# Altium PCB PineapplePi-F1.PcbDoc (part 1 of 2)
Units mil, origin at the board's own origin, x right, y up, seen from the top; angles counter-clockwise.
Board outline 1965 x 3150 mil, 2 copper layers (Top Layer, Bottom Layer); 93 components, 95 nets, 510 pads, 397 vias.
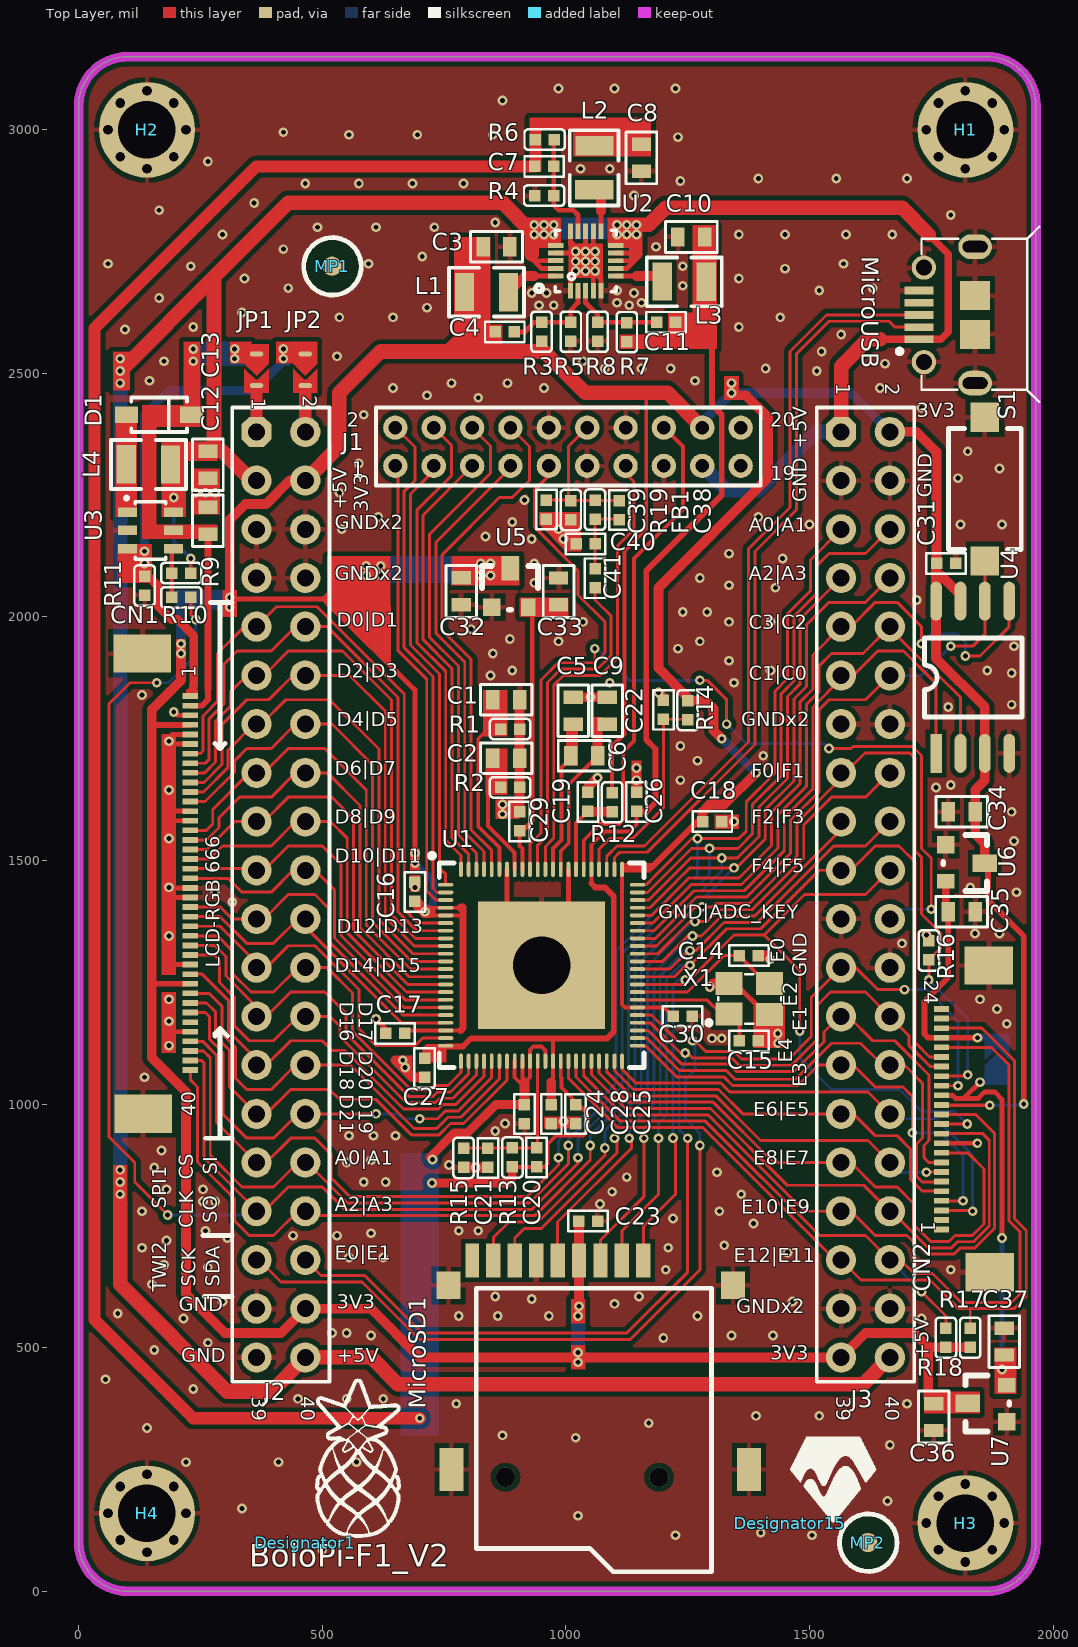
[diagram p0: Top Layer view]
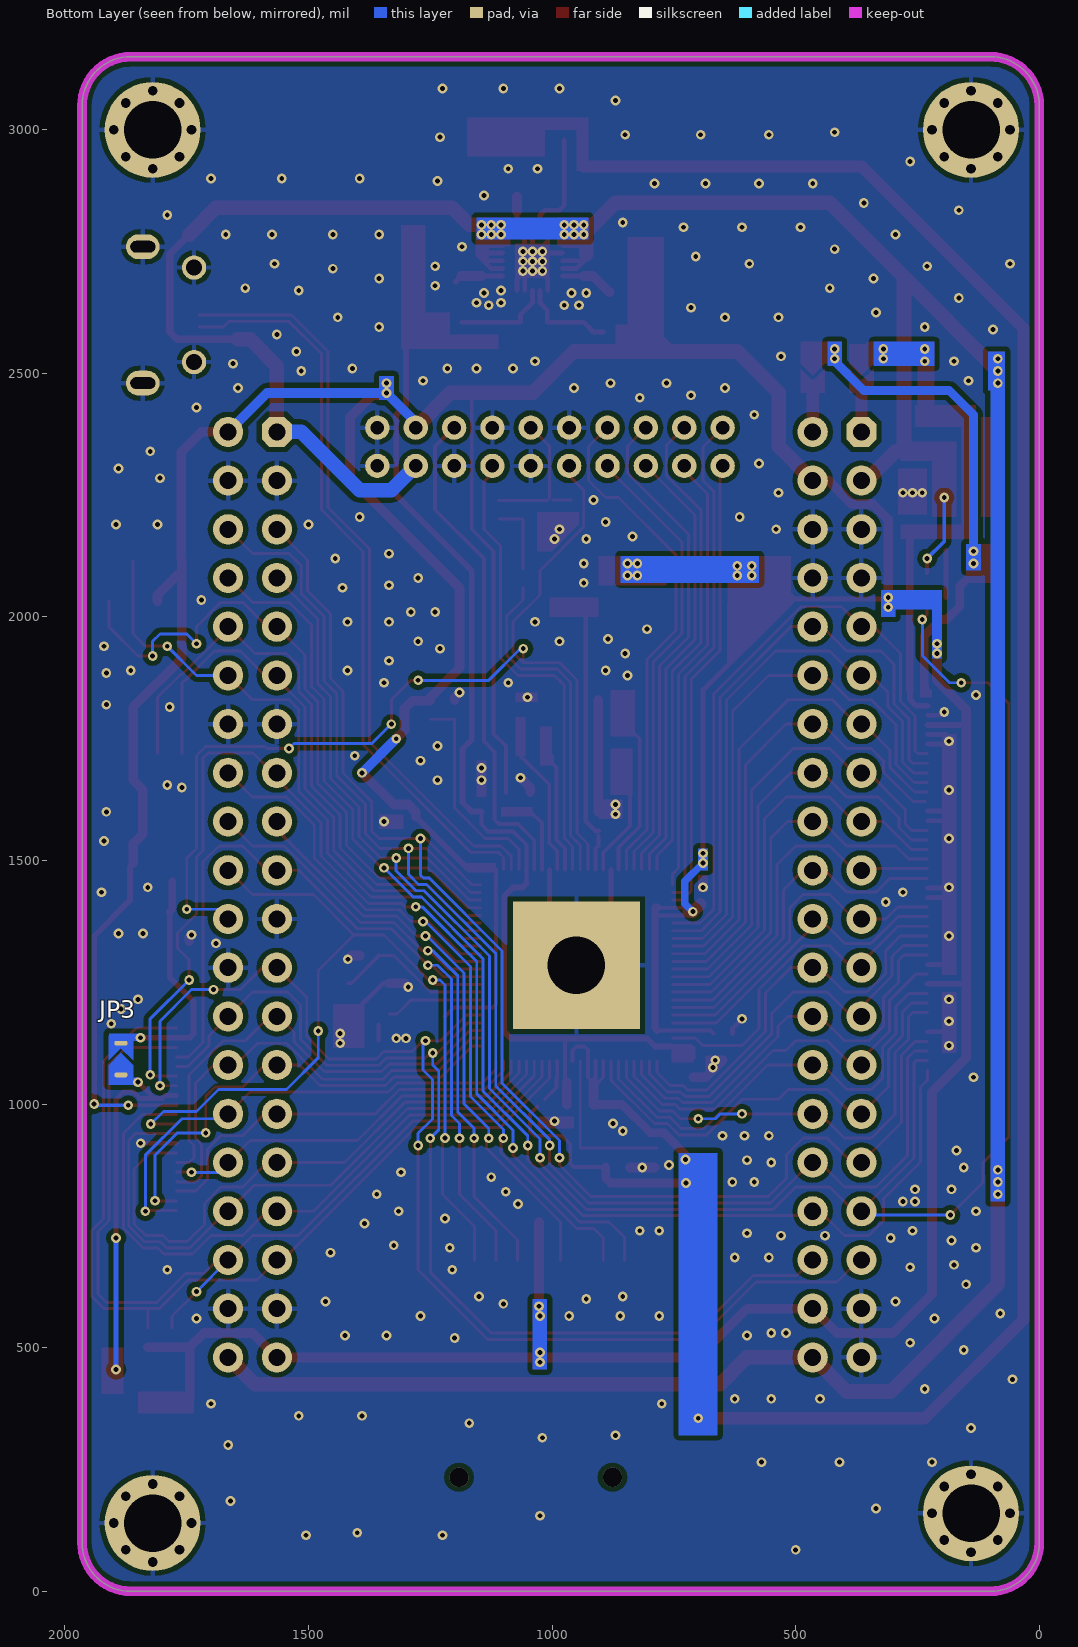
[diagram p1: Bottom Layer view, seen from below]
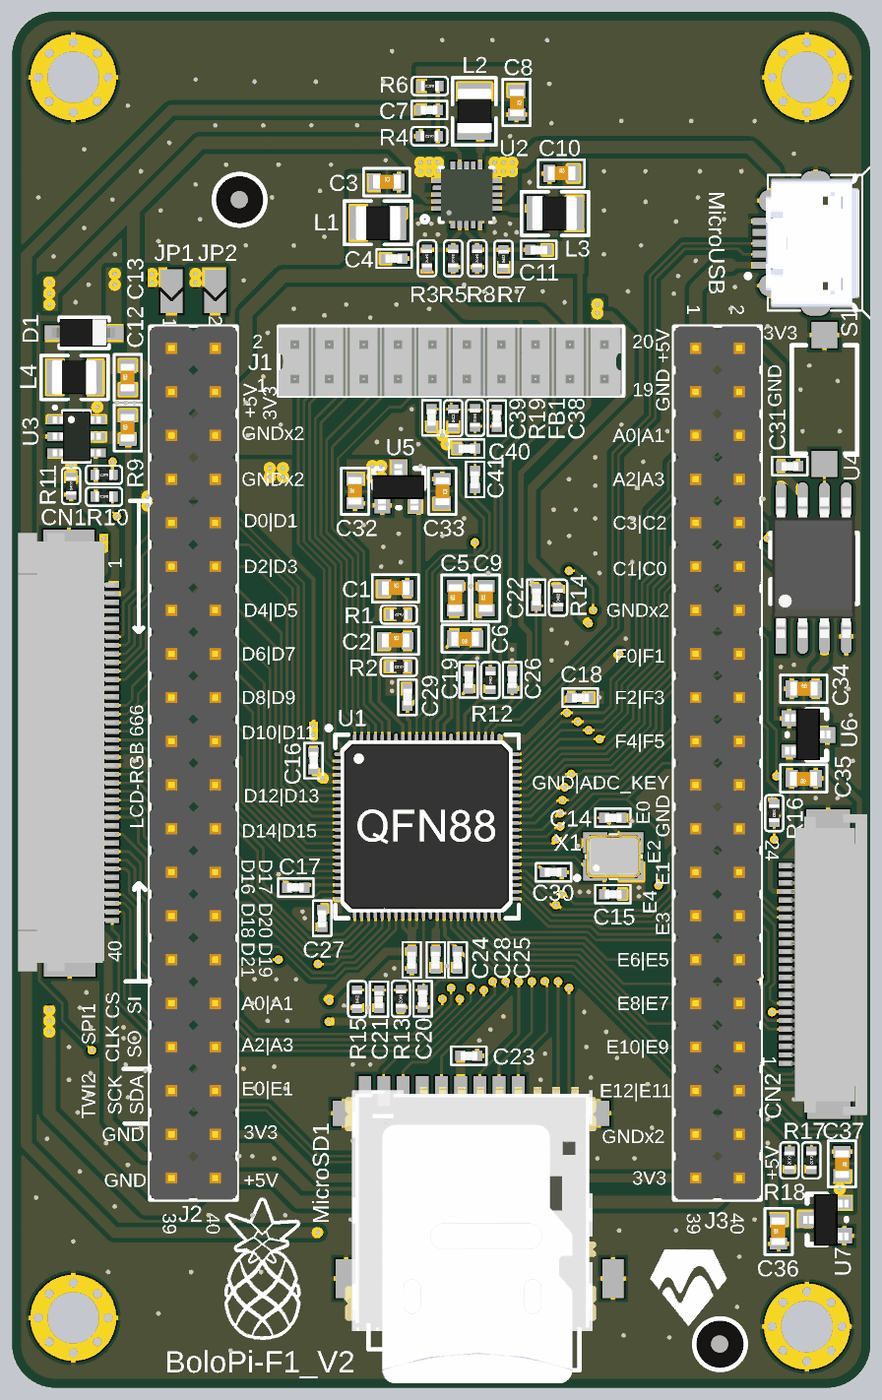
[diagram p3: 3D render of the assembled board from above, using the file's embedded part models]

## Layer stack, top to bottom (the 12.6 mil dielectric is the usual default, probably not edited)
Top Layer: signal copper 1.4
Dielectric: dielectric 12.6, FR-4, Dk 4.8
Bottom Layer: signal copper 1.4

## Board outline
0,100 ccw(c100,100) 100,0 1865,0 ccw(c1865,100) 1965,100 1965,3050 ccw(c1865,3050) 1865,3150 100,3150 ccw(c100,3050) 0,3050

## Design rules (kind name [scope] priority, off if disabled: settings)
Clearance [All] p1: gap=10
PolygonConnect [InNet('AGND') vs IsVia] p1: connectstyle=Direct reliefconductorwidth=10 reliefentries=4 polygonreliefangle="90 Angle"
PolygonConnect PolygonConnect_1 [All] p2: connectstyle=Relief reliefconductorwidth=10 reliefentries=4 polygonreliefangle="90 Angle"
RoutingVias [All] p1: holewidth=28 width=50 viastyle="Through Hole" minholewidth=28 minwidth=50 maxholewidth=28 maxwidth=50
SilkscreenOverComponentPads [All] p1: minsilkscreentomaskgap=10
SolderMaskExpansion [All] p1: expansion=4
Width [All] p1: maxlimit=50 minlimit=6 preferedwidth=30
27 further rules are at their usual default settings.

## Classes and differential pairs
component class PineapplePi-F1: C1 C2 C3 C4 C5 C6 C7 C8 C9 C10 C11 C12 C13 C14 C15 C16 C17 C18 C19 C20 C21 C22 C23 C24 C25 C26 C27 C28 C29 C30 C31 C32 C33 C34 C35 C36 C37 C38 C39 C40 C41 CN1 CN2 D1 FB1 J1 J2 J3 JP1 JP2 JP3 L1 L2 L3 L4 MicroSD1 MicroUSB MP1 MP2 R1 R2 R3 R4 R5 R6 R7 R8 R9 R10 R11 R12 R13 R14 R15 R16 R17 R18 R19 S1 U1 U2 U3 U4 U5 U6 U7 X1

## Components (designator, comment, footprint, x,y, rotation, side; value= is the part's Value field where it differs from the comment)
C1 "0402" 0603AC 850,1830 r0 top
C2 "0402" 0603AC 850,1710 r0 top
C3 "0402" 0603AC 830,2760 r0 top
C4 "0402" 0402AC 855,2585 r0 top
C5 "0402" 0603AC 1015,1780 r90 top
C6 "0402" 0603AC 1065,1715 r180 top
C7 "0402" 0402AC 936,2925 r0 top
C8 "0402" 0603AC 1155,2970 r270 top
C9 "0402" 0603AC 1085,1780 r90 top
C10 "0402" 0603AC 1230,2780 r0 top
C11 "0402" 0402AC 1225,2605 r180 top
C12 "0402" 0603AC 265,2170 r90 top
C13 "0402" 0603AC 265,2285 r90 top
C14 "0402" 0402AC 1395,1305 r180 top
C15 "0402" 0402AC 1395,1130 r180 top
C16 "0402" 0402AC 690,1455 r270 top
C17 "0402" 0402AC 630,1145 r0 top
C18 "0402" 0402AC 1320,1580 r180 top
C19 "0402" 0402AC 1045,1640 r270 top
C20 "0402" 0402AC 940,910 r270 top
C21 "0402" 0402AC 840,870 r90 top
C22 "0402" 0402AC 1200,1829 r270 top
C23 "0402" 0402AC 1065,760 r180 top
C24 "0402" 0402AC 915,960 r90 top
C25 "0402" 0402AC 1020,960 r90 top
C26 "0402" 0402AC 1145,1640 r270 top
C27 "0402" 0402AC 710,1055 r90 top
C28 "0402" 0402AC 970,960 r90 top
C29 "0402" 0402AC 905,1600 r270 top
C30 "0402" 0402AC 1220,1180 r0 top
C31 "0402" 0402AC 1800,2110 r180 top
C32 "0402" 0603AC 785,2025 r90 top
C33 "0402" 0603AC 985,2080 r270 top
C34 "0402" 0603AC 1785,1600 r0 top
C35 "0402" 0603AC 1840,1395 r180 top
C36 "0402" 0603AC 1755,330 r90 top
C37 "0402" 0603AC 1900,540 r270 top
C38 "0402" 0402AC 1110,2200 r90 top
C39 "0402" 0402AC 960,2240 r270 top
C40 "0402" 0402AC 1060,2150 r180 top
C41 "0402" 0402AC 1060,2060 r90 top
CN1 "RGB_LCD_40P" FH19C-40S-0.5SH 130,1925 r270 top
CN2 "Header 24" FH19C-24S-0.5SH 1870,655 r90 top
D1 "Diode" SOD123 165,2415 r180 top
Designator1 "Comment" ? 465,100 r0 top
Designator15 "Comment" 4.5MM-Digital-OVERLAY 1460,140 r0 top
FB1 "CD43" 0402AR 1060,2240 r270 top
H1 "M3-HOLE" M3-HOLE 1820,3000 r0 top
H2 "M3-HOLE" M3-HOLE 140,3000 r0 top
H3 "M3-HOLE" M3-HOLE 1820,140 r0 top
H4 "M3-HOLE" M3-HOLE 140,160 r0 top
J1 "Header 10X2" HDR2X10-2.0mm 650,2310 r0 top
J2 "Header 20X2" HDR2X20 365,2380 r270 top
J3 "Header 20X2" HDR2X20 1565,2380 r270 top
JP1 "SW-PAD-2" SW-PAD-2 340,2560 r270 top
JP2 "SW-PAD-2" SW-PAD-2 440,2560 r270 top
JP3 "SW-PAD-2" SW-PAD-2 1860,1040 r90 bottom
L1 "CD43" 2520 840,2665 r0 top
L2 "CD43" 2520 1060,2925 r90 top
L3 "CD43" 2520 1240,2690 r180 top
L4 "CD43" 2520 140,2315 r180 top
MicroSD1 "MicroSD" MicroSD 780,240 r0 top
MicroUSB "MicroUSB-DIP" MICRO_USB_DIP 1840,2480 r90 top (schematic designator MicroUSB-DIP1)
MP1 "MARKPOINT" MARKPOINT 520,2720 r0 top
MP2 "MARKPOINT" MARKPOINT 1620,100 r0 top
R1 "0402" 0402AR 905,1770 r180 top
R2 "0402" 0402AR 905,1650 r180 top
R3 "0402" 0402AR 950,2605 r270 top
R4 "0402" 0402AR 975,2865 r180 top
R5 "0402" 0402AR 1010,2605 r270 top
R6 "0402" 0402AR 976,2980 r180 top
R7 "0402" 0402AR 1125,2565 r90 top
R8 "0402" 0402AR 1065,2605 r270 top
R9 "0402" 0402AR 230,2090 r180 top
R10 "0402" 0402AR 230,2040 r180 top
R11 "0402" 0402AR 135,2045 r90 top
R12 "0402" 0402AR 1095,1600 r90 top
R13 "0402" 0402AR 890,910 r270 top
R14 "0402" 0402AR 1250,1789 r90 top
R15 "0402" 0402AR 790,870 r90 top
R16 "0402" 0402AR 1745,1335 r270 top
R17 "0402" 0402AR 1830,540 r270 top
R18 "0402" 0402AR 1780,540 r270 top
R19 "0402" 0402AR 1010,2200 r90 top
S1 "SW-PB" SW-SMD1 1860,2110 r90 top
U1 "F1C100S" QFN88-10X10 950,1285 r0 top
U2 "EA3036QDR" QFN20-3x3-0.4 1000,2670 r0 top
U3 "AP3019_SOT-23-6" SOT23-6 100,2215 r90 top
U4 "W25QXX" SO-8M 1760,1720 r90 top
U5 "ME6206_3V0" SOT-23 800,2140 r0 top
U6 "ME6206_2V8" SOT-23 1900,1580 r270 top
U7 "ME6206_1V2" SOT-23 1785,300 r90 top
X1 "XTAL-24MHz" XTAL-3225 1335,1185 r0 top

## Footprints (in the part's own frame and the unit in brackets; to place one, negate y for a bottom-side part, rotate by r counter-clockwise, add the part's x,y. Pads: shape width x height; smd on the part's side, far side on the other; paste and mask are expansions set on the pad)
4.5MM-Digital-OVERLAY [mil]
  silkscreen extent 1,1 177,177
0402AC [mm]
  rect 0.6x0.6 smd: 1(0,0) 2(0.991,0)
  silkscreen extent -0.53,-0.53 1.52,0.53, body extent -0.03,-0.25 0.97,0.28, height 0.36
0402AR [mm]
  rect 0.6x0.6 smd: 1(0,0) 2(0.991,0)
  silkscreen extent -0.55,-0.53 1.55,0.53, body extent -0.03,-0.3 1.01,0.3, height 0.34
0603AC [mm]
  rect 0.7x1 smd: 1(0,0) 2(1.4,0)
  silkscreen extent -0.65,-0.8 2.05,0.8, body extent -0.09,-0.38 1.51,0.42, height 0.3
2520 [mm]
  rect 1x2 smd: 1(-1.219,0.051) 2(1.076,0.035)
  silkscreen extent -2.03,-1.22 1.88,1.32, body extent -1.35,-0.97 1.25,1.03, height 0.9
FH19C-24S-0.5SH [mm]
  rect 0.3x0.8 smd: 1(2.221,2.515) 2(2.721,2.515) 3(3.221,2.515) 4(3.721,2.515) 5(4.221,2.515) 6(4.721,2.515) 7(5.221,2.515) 8(5.721,2.515) 9(6.221,2.515) 10(6.721,2.515) 11(7.221,2.515) 12(7.721,2.515) 13(8.221,2.515) 14(8.721,2.515) 15(9.221,2.515) 16(9.721,2.515) 17(10.221,2.515) 18(10.721,2.515) 19(11.221,2.515) 20(11.721,2.515) 21(12.221,2.515) 22(12.721,2.515) 23(13.221,2.515) 24(13.721,2.515)
  rect 2x2.54 smd: 25(0,0) 26(15.989,0.051)
  body extent -0.79,-2.24 16.71,2.66, height 1.8
FH19C-40S-0.5SH [mm]
  rect 0.3x0.8 smd: 1(2.221,2.515) 2(2.721,2.515) 3(3.221,2.515) 4(3.721,2.515) 5(4.221,2.515) 6(4.721,2.515) 7(5.221,2.515) 8(5.721,2.515) 9(6.221,2.515) 10(6.721,2.515) 11(7.221,2.515) 12(7.721,2.515) 13(8.221,2.515) 14(8.721,2.515) 15(9.221,2.515) 16(9.721,2.515) 17(10.221,2.515) 18(10.721,2.515) 19(11.221,2.515) 20(11.721,2.515) 21(12.221,2.515) 22(12.721,2.515) 23(13.221,2.515) 24(13.721,2.515) 25(14.221,2.515) 26(14.721,2.515) 27(15.221,2.515) 28(15.721,2.515) 29(16.221,2.515) 30(16.721,2.515) 31(17.221,2.515) 32(17.721,2.515) 33(18.221,2.515) 34(18.721,2.515) 35(19.221,2.515) 36(19.721,2.515) 37(20.221,2.515) 38(20.721,2.515) 39(21.221,2.515) 40(21.721,2.515)
  rect 2x3 smd: 41(0,0) 42(24.003,0.051)
  body extent -0.81,-2.95 24.69,2.65, height 2
HDR2X10-2.0mm [mm]
  round 1.27 hole 0.7: 1(0,0) 2(0,2) 3(2,0) 4(2,2) 5(4,0) 6(4,2) 7(6,0) 8(6,2) 9(8,0) 10(8,2) 11(10,0) 12(10,2) 13(12,0) 14(12,2) 15(14,0) 16(14,2) 17(16,0) 18(16,2) 19(18,0) 20(18,2)
  silkscreen extent -1.02,-1.02 19.05,3.05, body extent -1.02,-1.02 18.88,2.98, height 5.55
HDR2X20 [mil]
  oct 62x62 hole 35: 1(0,0)
  round 62 hole 35: 2(0,100) 3(100,0) 4(100,100) 5(200,0) 6(200,100) 7(300,0) 8(300,100) 9(400,0) 10(400,100) 11(500,0) 12(500,100) 13(600,0) 14(600,100) 15(700,0) 16(700,100) 17(800,0) 18(800,100) 19(900,0) 20(900,100) 21(1000,0) 22(1000,100) 23(1100,0) 24(1100,100) 25(1200,0) 26(1200,100) 27(1300,0) 28(1300,100) 29(1400,0) 30(1400,100) 31(1500,0) 32(1500,100) 33(1600,0) 34(1600,100) 35(1700,0) 36(1700,100) 37(1800,0) 38(1800,100) 39(1900,0) 40(1900,100)
  silkscreen extent -50,-50 1950,150, body extent -50,-50 1950,150, height 398
M3-HOLE [mil]
  round 196.85 hole 118.11: 1(0,0)
  round 20 hole 20: 2(0,80) 3(55,55) 4(80,0) 5(55,-55) 6(0,-80) 7(-55,-55) 8(-80,0) 9(-55,55)
MARKPOINT [mm]
  round 1 smd mask+0.9: 0(0,0)
  Top Layer pour cut-out: -1.486,-0.009 -1.372,-0.583 -1.047,-1.07 -0.56,-1.395 0.014,-1.509 0.014,-1.509 0.588,-1.395 1.074,-1.07 1.399,-0.583 1.514,-0.009 1.514,-0.009 1.399,0.565 1.074,1.052 0.588,1.377 0.014,1.491 0.014,1.491 -0.56,1.377 -1.047,1.052 -1.372,0.565 -1.486,-0.009
  silkscreen extent -1.48,-1.51 1.52,1.49
MICRO_USB_DIP [mm]
  oval 1.3x1.75 hole 0.6 slot 1.3 at 90 deg: 0(0,0) 0(7.112,0)
  round 1.27 hole 0.85: 0(1.1,2.667) 0(6.027,2.667)
  round 1.27 on Top Paste: 0(1.1,2.667) 1(6.027,2.667)
  rect 1.5x1.55 smd: 0(2.54,0) 0(4.572,0)
  rect 0.4x1.5 smd: 1(2.286,2.921) 2(2.921,2.921) 3(3.556,2.921) 4(4.191,2.921) 5(4.826,2.921)
  oval 1.3x1.75 on Top Paste: 2(0,0) 3(7.112,0)
  silkscreen extent -0.98,-3.34 8.15,4.06, body extent -0.54,-2.54 7.66,2.89, height 2.68
MicroSD [mil]
  rect 49.21x57.09 smd: 0(-21,388) 0(563,388)
  rect 49.21x88.58 smd: 0(-15,10) 0(596,10)
  rect 29.53x68.9 smd: 1(379,439) 2(335,439) 3(291,439) 4(247,439) 5(203,439) 6(159,439) 7(115,439) 8(71,439)
  rect 27.56x68.9 smd: 9(28,439)
  silkscreen extent 36,-200 519,382, body extent -17,-230 557,449, height 57
QFN20-3x3-0.4 [mm]
  rect 0.26x0.8 smd: 1(0.229,0) 2(0.629,0) 3(1.029,0) 4(1.429,0) 5(1.829,0) 11(1.829,3.099) 12(1.429,3.099) 13(1.029,3.099) 14(0.629,3.099) 15(0.229,3.099)
  rect 0.8x0.26 smd: 6(2.591,0.755) 7(2.591,1.155) 8(2.591,1.555) 9(2.591,1.955) 10(2.591,2.355) 16(-0.533,2.357) 17(-0.533,1.957) 18(-0.533,1.557) 19(-0.533,1.157) 20(-0.533,0.757)
  silkscreen extent -0.56,-0.05 2.62,3.15, body extent -0.47,0.03 2.55,3.05, height 0.75
QFN88-10X10 [mm]
  oval 0.8x0.2 smd: 1(-5,4.2) 2(-5,3.8) 3(-5,3.4) 4(-5,3) 5(-5,2.6) 6(-5,2.2) 7(-5,1.8) 8(-5,1.4) 9(-5,1) 10(-5,0.6) 11(-5,0.2) 12(-5,-0.2) 13(-5,-0.6) 14(-5,-1) 15(-5,-1.4) 16(-5,-1.8) 17(-5,-2.2) 18(-5,-2.6) 19(-5,-3) 20(-5,-3.4) 21(-5,-3.8) 22(-5,-4.2) 45(5,-4.2) 46(5,-3.8) 47(5,-3.4) 48(5,-3) 49(5,-2.6) 50(5,-2.2) 51(5,-1.8) 52(5,-1.4) 53(5,-1) 54(5,-0.6) 55(5,-0.2) 56(5,0.2) 57(5,0.6) 58(5,1) 59(5,1.4) 60(5,1.8) 61(5,2.2) 62(5,2.6) 63(5,3) 64(5,3.4) 65(5,3.8) 66(5,4.2)
  oval 0.2x0.8 smd: 23(-4.2,-5) 24(-3.8,-5) 25(-3.4,-5) 26(-3,-5) 27(-2.6,-5) 28(-2.2,-5) 29(-1.8,-5) 30(-1.4,-5) 31(-1,-5) 32(-0.6,-5) 33(-0.2,-5) 34(0.2,-5) 35(0.6,-5) 36(1,-5) 37(1.4,-5) 38(1.8,-5) 39(2.2,-5) 40(2.6,-5) 41(3,-5) 42(3.4,-5) 43(3.8,-5) 44(4.2,-5) 67(4.2,5) 68(3.8,5) 69(3.4,5) 70(3,5) 71(2.6,5) 72(2.2,5) 73(1.8,5) 74(1.4,5) 75(1,5) 76(0.6,5) 77(0.2,5) 78(-0.2,5) 79(-0.6,5) 80(-1,5) 81(-1.4,5) 82(-1.8,5) 83(-2.2,5) 84(-2.6,5) 85(-3,5) 86(-3.4,5) 87(-3.8,5) 88(-4.2,5)
  rect 6.64x6.64 hole 3: 89(0,0)
  silkscreen extent -5.84,-5.33 5.33,5.84, body extent -5.04,-5.01 4.98,5.01, height 0.85
SO-8M [mil]
  rect 80x24 smd: 1(0,0)
  oval 80x24 smd: 2(0,-50) 3(0,-100) 4(0,-150) 5(312.6,-150) 6(312.6,-100) 7(312.6,-50) 8(312.6,0)
  silkscreen extent 74,-176 237,24, body extent -4,-170 318,20, height 67
SOD123 [mm] "SOD-123; 2 Leads; Body 2.7 x 1.6 mm, (LxW)"
  rect 1.2x0.85 smd: 1(1.7,0) 2(-1.7,0)
  silkscreen extent -1.45,-0.9 1.45,0.9, body extent -1.8,-0.81 1.9,0.79, height 1.27
SOT23-6 [mm] "SOT-23/SC-74A; 5 Leads; Body 3.1 x 3 mm, inc. leads (LxW max)"
  rect 0.5x1 smd: 1(0,0) 2(-0.95,0) 3(-1.9,0) 4(-1.9,-2.4) 5(-0.95,-2.4) 6(0,-2.4)
  silkscreen extent -2.45,-2 0.79,0.1, body extent -2.39,-2.62 0.51,0.18, height 1.45
SOT-23 [mil]
  rect 36x36 smd: 1(47.76,-120.28)
  rect 30x36 smd: 2(122.76,-120.28)
  rect 36x50 smd: 3(85.76,-40.28)
  silkscreen extent 28,-125 143,-35, body extent 25,-130 143,-26, height 43
SW-PAD-2 [mil]
  oval 10x27.56 smd: 1(20,25) 2(85,25)
  Top Layer region: 0,0 40,0 65,25 40,50 0,50
  Top Layer region: 50,0 75,25 50,50 100,50 100,0
SW-SMD1 [mil]
  rect 60x59.06 smd: 1(5,0) 2(300,0)
  silkscreen extent 29,-75 277,75, body extent -2,-77 308,75, height 98
XTAL-3225 [mm]
  rect 1.4x1.2 smd: 1(0,0) 2(2.108,-0.025) 3(2.108,1.6) 4(0,1.6)
  silkscreen extent -1.17,-0.57 2.72,2.08, body extent -0.53,-0.46 2.67,2.04, height 0.61
? [mil]
  silkscreen extent 21,10 196,336

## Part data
C1 C2 C3 C4 C5 C6 C7 C8 C9 C10 C11 C12 C13 C14 C15 C16 C17 C18 C19 C20 C21 C22 C23 C24 C25 C26 C27 C28 C29 C30 C31 C32 C33 C34 C35 C36 C37 C38 C39 C40 C41: library part Cap, "Capacitor"
CN2: "Header, 24-Pin"
D1: "Default Diode"
FB1 L1 L2 L3 L4: library part Inductor
J1: "Header, 10-Pin, Dual row"
J2 J3: "Header, 20-Pin, Dual row"
R1 R2 R4 R5 R19: library part Res1, "Resistor"
R3 R6 R7 R8 R9 R10 R11 R12 R13 R14 R15 R16 R17 R18: library part Res1
S1: "Switch"
U3: library part AP3019
U5 U6 U7: library part ME6206
X1: library part XTAL-SMD

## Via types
v1: diameter 20, hole 10, Top Layer to Bottom Layer, tented both sides, 286 vias
v2: diameter 20, hole 10, Top Layer to Bottom Layer, 109 vias
v3: diameter 39.37, hole 39.37, Top Layer to Bottom Layer, 2 vias

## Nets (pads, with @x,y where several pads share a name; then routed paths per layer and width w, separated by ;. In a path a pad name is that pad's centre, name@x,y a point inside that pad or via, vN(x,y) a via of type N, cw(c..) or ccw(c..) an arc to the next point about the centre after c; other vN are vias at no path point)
+5V: C13.2 J1.17 J2.3 J2.40 J3.1 J3.40 L4.1 MicroUSB.1@1725,2570 R9.1 U2.7 U2.8 U2.9 U2.10 U2.16 U2.18 U2.19 U3.6 | length 7247.6
  Top Layer w8: R9.1@230,2090 v2(230,2120)
  Top Layer w10: 930,2745 930,2735 933.72,2731.28 ; 930,2762.78 U2.16@979,2762.78 ; U2.19@979,2715.54 949.46,2715.54 933.72,2731.28 ; U2.18@979,2731.28 933.72,2731.28 ; U2.7@1102,2715.49 1125.49,2715.49 1141.24,2731.24 ; U2.8@1102,2731.24 1141.24,2731.24 ; U2.9@1102,2746.98 1146.72,2746.98 ; U2.10@1102,2762.73 1132.27,2762.73 1152.5,2742.5 1141.24,2731.24
  Top Layer w15: 1645,2570 MicroUSB.1@1725,2570 1770,2570 1785,2585 1785,2745 1745,2785
  Top Layer w30: v2(85,815) 85,630 305,410 395,410 J2.40@465,480 600,480 655,425 1610,425 J3.40@1665,480 ; v2@85,2510 90,2510 277.55,2697.55 ; J2.3@365,2280 355,2280 294.88,2340.12 C13.2@265,2340.12 277.55,2352.67 277.55,2697.55 ; 930,2745 930,2762.78 930,2790 870,2850 430,2850 277.55,2697.55 ; v2(1125,2805) v2(1145,2805) 1170,2805 1205,2840 1690,2840 1745,2785 ; J3.1@1565,2380 1565,2515 1620,2570 1645,2570
  Bottom Layer w8: v2(195,2245) 195,2155 v2(230,2120)
  Bottom Layer w30: 85,855 v2(85,865) v2(85,2480) ; J1.17@1279.92,2310 1329.92,2260 1395,2260 1515,2380 J3.1@1565,2380
  other v2: 85,840 85,2505 85,2530 935,2785 955,2785 975,2785 1105,2785 1125,2785 1145,2785 935,2805 955,2805 975,2805 1105,2805
AGND: C1.2 C2.2 C3.2 C5.2 C8.2 C9.2 C10.1 C12.2 C13.1 C14.1 C15.1 C16.1 C17.1 C18.1 C19.1 C21.1 C22.1 C23.1 C24.1 C25.1 C26.1 C27.1 C28.1 C29.1 C30.2 C31.1 C32.1 C33.1 C34.1 C35.1 C36.1 C37.1 C39.2 C40.2 CN1.3 CN1.5 CN1.6 CN1.13 CN1.14 CN1.21 CN1.22 CN1.29 CN1.36 CN1.41 CN1.42 CN2.10 CN2.23 CN2.25 CN2.26 H1.1 H1.2 H1.3 H1.4 H1.5 H1.6 H1.7 H1.8 H1.9 H2.1 H2.2 H2.3 H2.4 H2.5 H2.6 H2.7 H2.8 H2.9 H3.1 H3.2 H3.3 H3.4 H3.5 H3.6 H3.7 H3.8 H3.9 H4.1 H4.2 H4.3 H4.4 H4.5 H4.6 H4.7 H4.8 H4.9 J1.10 J1.11 J1.14 J1.15 J1.19 J1.20 J2.5 J2.6 J2.7 J2.8 J2.37 J2.39 J3.3 J3.4 J3.13 J3.14 J3.21 J3.24 J3.37 J3.38 MicroSD1.0 MicroSD1.6 MicroUSB.0@1735,2523.31 MicroUSB.0@1735,2717.28 MicroUSB.0@1840,2480 MicroUSB.0@1840,2580 MicroUSB.0@1840,2660 MicroUSB.0@1840,2760 MicroUSB.5 R1.1 R2.1 R4.2 R5.2 R8.2 R11.1 R15.1 R16.1 R19.1 S1.2 U1.74 U1.82 U1.89 U2.1 U2.4 U2.5 U2.12 U2.13 U2.15 U2.17 U3.2 U4.4 U5.1 U6.1 U7.1 X1.2 X1.4 | length 1779.2
  Top Layer w10: v1(185,1445) 186.15,1443.85 CN1.21@229,1443.85 ; 185,1580 186.65,1581.65 CN1.14@229,1581.65 ; 188.67,1601.33 CN1.13@229,1601.33 ; 190,1425 190.83,1424.17 CN1.22@229,1424.17 ; v1@190.87,1739.13 CN1.6@229,1739.13 ; 191.19,1758.81 CN1.5@229,1758.81 ; 191.42,1148.58 CN1.36@229,1148.58 ; 195,1286.37 CN1.29@229,1286.37 ; v1(195,1805) 201.82,1798.18 CN1.3@229,1798.18 ; v1(610,1175) 630,1155 C17.1@630,1145 ; U1.82@879.13,1481.85 879.13,1390.87 U1.89@950,1320 ; U1.89@950,1285 1005.12,1340.12 U1.74@1005.12,1481.85 ; U2.17@979,2747.03 v1@1037.03,2747.03 ; U2.1@1009,2670 1009,2694 1015,2700 ; 1009.01,2764.01 1009.01,2770.99 ; U2.15@1009.01,2792 1009.01,2770.99 ; 1015,2765 1009.01,2770.99 ; 1040.5,2760.5 U2.13@1040.5,2792 ; U2.4@1056.24,2670 v1@1056.24,2706.24 ; v1@1056.25,2753.75 U2.12@1056.25,2792 ; 1065,2700 1071.99,2693.01 U2.5@1071.99,2670 ; X1.4@1335,1248 1347,1248 1411,1184 X1.2@1418,1184 ; CN2.10@1771,919.61 v1(1844.61,919.61)
  Top Layer w20: C27.1@710,1055 684.9,1055 650,1089.9 650,1090 ; R15.1@790,870 C21.1@840,870 ; C29.1@905,1600 R2.1@905,1650 C1.2@905,1830 ; C19.1@1045,1640 1045,1650 v1(1065,1670) ; v1(1190,1845) 1200,1835 C22.1@1200,1829 ; v1(1295.37,1240.37) 1303,1248 X1.4@1335,1248 ; C14.1@1395,1305 1411.62,1305 v1(1419.32,1297.3) ; v1(1740,1347.47) 1745,1342.47 R16.1@1745,1335 ; 650,1090 v1(665,1090) 650,1090
  other v1: 500,85 1225,115 1505,115 1400,120 1025,155 335,170 1660,185 220,265 410,265 570,265 1665,300 1020,315 870,320 140,335 1170,345 1390,360 1520,360 775,385 1700,385 450,395 550,395 625,395 235,415 55,435 155,495 265,510 1200,520 600,525 1340,525 1425,525 520,530 550,530 215,560 1730,560 780,565 860,565 965,565 1270,565 80,570 1100,590 295,595 1465,595 930,600 855,605 1150,605 150,630 1205,660 1790,660 265,665 175,670 555,685 625,685 1455,695 130,705 1210,705 1325,710 180,720 305,725 440,730 530,730 600,735 260,740 780,740 820,740 1385,755 1220,765 130,780 1315,780 1070,795 255,800 280,800 1360,815 1095,820 180,825 255,825 585,840 630,840 1125,850 1310,860 155,870 815,870 760,875 550,880 600,885 170,905 555,935 605,935 650,935 855,945 875,960 995,965 135,1055 670,1075 185,1120 1435,1125 1300,1135 1320,1135 1435,1145 1905,1165 185,1170 1885,1195 185,1215 1850,1215 1690,1330 185,1345 1840,1350 1890,1350 315,1415 280,1435 1925,1435 690,1445 1830,1445 1920,1540 185,1545 1345,1580 870,1595 1915,1600 870,1615 185,1645 1760,1650 1790,1655 1145,1665 1235,1665 1145,1690 1270,1705 1405,1715 1235,1735 185,1745 1785,1815 1915,1820 1050.32,1835.12 130,1840 1090,1865 1345,1865 845,1880 1915,1885 890,1890 1420,1890 1865,1890 1335,1910 850,1925 1230,1935 1920,1940 985,1950 1275,1950 885,1955 805,1975 1035,1990 1335,1990 1420,1990 1240,2010 1290,2010 1720,2035 1430,2060 1335,2065 935,2070 1275,2080 935,2110 1445,2120 1335,2130 930,2160 835,2165 540,2180 1500,2190 1810,2190 1895,2190 890,2195 615,2205 1395,2205 915,2240 240,2255 260,2255 280,2255 535,2255 1805,2285 1890,2305 575,2315 1825,2340 585,2415 1730,2430 820,2450 715,2455 645,2470 955,2470 1645,2470 765,2480 880,2480 145,2485 1265,2485 1515,2505 1080,2510 1155,2510 1215,2510 1410,2510 1655,2520 175,2525 1035,2525 530,2535 1525,2545 1565,2580 95,2590 235,2595 1355,2595 535,2615 645,2615 1440,2615 335,2625 715,2635 945,2640 975,2640 1130,2640 1105,2645 1155,2645 165,2655 930,2665 960,2665 1140,2665 1105,2670 1520,2670 430,2675 1630,2675 1240,2680 340,2695 1355,2695 1020,2710 1040,2710 1060,2710 1450,2715 230,2720 1240,2720 60,2725 595,2725 1570,2725 1020,2730 1040,2730 1060,2730 705,2740 1020,2750 1040,2750 1060,2750 420,2755 1185,2760 295,2785 1355,2785 1450,2785 1575,2785 1670,2785 490,2800 610,2800 730,2800 855,2810 1790,2825 165,2835 360,2850 1140,2865 465,2890 575,2890 685,2890 790,2890 1235,2895 1395,2900 1555,2900 1700,2900 1030,2920 1090,2920 265,2935 1230,2985 555,2990 695,2990 850,2990 420,2995 870,3060 985,3085 1100,3085 1225,3085
  other v2: 995,2160 985,2180
AVCC: C29.2 C33.2 U1.80 U5.2 | length 551.6
  Top Layer w8: C29.2@905,1550 905,1530 910.63,1524.37 U1.80@910.63,1481.85
  Top Layer w10: C29.2@905,1561 911,1561 930.9,1580.9 930.9,2019.72 U5.2@922.76,2019.72
CSI_AVDD: C35.2 CN2.21 JP3.2 U6.2 | length 447.9
  Top Layer w12: C35.2@1784.88,1395 1784.88,1259.88 1736,1211 1736,1144 1743.85,1136.15 CN2.21@1771,1136.15 v2(1845,1136.15)
  Top Layer w15: U6.2@1779.72,1457.24 1779.72,1400.16 C35.2@1784.88,1395
CSI_D0: CN2.6 J3.28 U1.46 | length 937.4
  Top Layer w6: U1.46@1146.85,1135.39 1166.22,1135.39 1232.62,1069 1329.23,1069 1347.23,1051 1471.15,1051 1545.15,1125 1605,1125 1650,1080 J3.28@1665,1080 1695,1080 1732.25,1042.75 1732.25,930.64 1720,918.38 1720,851.72 1731.72,840 1770.13,840 CN2.6@1771,840.87
CSI_D1: CN2.4 J3.27 U1.45 | length 982.4
  Top Layer w6: U1.45@1146.85,1119.65 1163.58,1119.65 1227.23,1056 1323.85,1056 1341.85,1038 1476.54,1038 1518.54,1080 J3.27@1565,1080 1590,1080 1635,1035 1692,1035 1711,1016 v2(1711,941) v2@1706,941 ; CN2.4@1771,801.5 v2(1815,801.5)
  Bottom Layer w6: v2(1711,941) 1769,941 1815,895 v2(1815,801.5)
CSI_D2: CN2.3 J3.30 U1.44 | length 990.2
  Top Layer w6: U1.44@1115.35,1088.15 1115.35,1071.57 1143.92,1043 1318.46,1043 1336.46,1025 1620,1025 J3.30@1665,980 ; CN2.3@1771,781.82 1830,781.82 1830,780 v2(1835,780)
  Bottom Layer w6: J3.30@1665,980 1675,970 1760,970 1835,895 v2(1835,780)
CSI_D3: CN2.5 J3.29 U1.43 | length 829.4
  Top Layer w6: U1.43@1099.61,1088.15 1099.61,1068.93 1138.54,1030 1313.08,1030 1363.08,980 J3.29@1565,980 1590,980 1635,935 1680,935 1707,908 1707,846.33 1732.15,821.19 CN2.5@1771,821.19
CSI_D4: CN2.7 J3.32 U1.42 | length 804.7
  Top Layer w6: U1.42@1083.86,1088.15 1083.86,1066.3 1133.15,1017 1307.69,1017 1399.69,925 1620,925 J3.32@1665,880 J3.32@1665,865 ; v2@1745,860 1745.56,860.56 CN2.7@1771,860.56
  Bottom Layer w6: J3.32@1665,880 1685,860 v2(1740,860)
CSI_D5: CN2.9 J3.31 U1.41 | length 1211.4
  Top Layer w6: U1.41@1068.11,1088.15 1068.11,1063.66 1127.77,1004 1302.31,1004 1426.31,880 J3.31@1565,880 1585,880 1635,830 1680,830 1713.76,796.24 1713.76,753 1748.77,718 1786.23,718 1798.6,730.37 1834.26,730.37 1858,754.11 1858,867 1825.07,899.93 CN2.9@1771,899.93
CSI_D6: CN2.11 J3.34 U1.40 | length 1289.6
  Top Layer w6: U1.40@1052.36,1088.15 1052.36,1061.02 1122.38,991 1296.92,991 1454.54,833.38 1611.62,833.38 J3.34@1665,780 1668.38,780 1743.38,705 1791.62,705 1803.99,717.37 1836.81,717.37 1869,749.56 1869,926 1855.7,939.3 CN2.11@1771,939.3
CSI_D7: CN2.13 J3.33 U1.39 | length 1366.9
  Top Layer w6: U1.39@1036.61,1088.15 1036.61,1058.39 1117,978 1291.54,978 1489.54,780 J3.33@1565,780 1585,780 1635,730 1700,730 1738,692 1797,692 1809.37,704.37 1839.37,704.37 1880,745 1880,940 1841.33,978.67 CN2.13@1771,978.67
CSI_DVDD: C37.2 CN2.15 JP3.1 U7.2 | length 740.4
  Top Layer w10: CN2.15@1771,1018.04 1793.69,1018.04 1800,1011.72 1816.72,1011.72 ; v2(1850,1045) 1816.72,1011.72 ; v2(1895,725) 1895,1010 1880,1025 1860,1025 1846.72,1011.72 1816.72,1011.72
  Bottom Layer w10: v2(1895,455) v2(1895,725)
CSI_HSYNC: CN2.16 J2.35 J3.23 U1.49 | length 2555.6
  Top Layer w6: J2.35@365,680 370,680 415,635 581.62,635 699.62,517 1132,517 1275,660 v2(1275,915) ; U1.49@1146.85,1182.64 1175.75,1182.64 1228.38,1130 v2(1260,1130) ; v2@1265,1130 1287,1108 1345.38,1108 1360.68,1092.7 1457.7,1092.7 1503.62,1138.62 1503.62,1218.62 J3.23@1565,1280 1595,1280 1640,1235 v2(1695,1235) ; CN2.16@1771,1037.72 v2(1805,1037.72)
  Bottom Layer w6: v2(1260,1130) 1265,1125 1265,1070 1245.69,1050.69 1245.69,969.31 1275,940 v2(1275,915) ; v2(1695,1235) 1740,1235 1805,1170 v2(1805,1037.72)
CSI_IOVDD: C3.1 C4.1 C16.2 C17.2 C18.2 C23.2 C30.1 C31.2 C32.2 C34.2 C36.2 CN1.4 CN1.31 CN2.14 J1.18 J2.4 J2.38 J3.2 J3.39 L1.1 MicroSD1.4 R3.2 R12.2 R14.2 R17.2 R18.2 U1.4 U1.5 U1.20 U1.50 U1.67 U4.3 U4.7 U4.8 U5.3 U6.3 U7.3 | length 11593.1
  Top Layer w8: C17.2@669,1145 675.14,1151.14 U1.20@753.15,1151.14 783.86,1151.14 ; 721.89,1403.11 U1.4@753.15,1403.11 783.11,1403.11 ; 722.64,1387.36 U1.5@753.15,1387.36 781.22,1387.36 ; R12.2@1095,1639 1095,1735 1120,1760 1120,2135 1165,2180 1165,2450 1155,2460 ; U1.67@1115.35,1481.85 1115.35,1204.65 1121.61,1198.39 U1.50@1146.85,1198.39 1201.61,1198.39 C30.1@1220,1180 ; CN2.14@1771,998.35 1771.63,997.72 v2(1870,997.72)
  Top Layer w10: v2(310,2040) 313,2037 503,2037 ; 635,2085 v2(620,2085) v2(590,2085) 551,2085 503,2037 ; v2@690,1490 v2(690,1495) v2(690,1515) 690,1850 503,2037
  Top Layer w12: 150,1247 CN1.31@229,1247 ; 150,1778.5 CN1.4@229,1778.5 ; v2(210,1925) v2(210,1945) ; 1160,1485 1175,1485 C18.2@1280,1590 ; U6.3@1859.72,1494.24 1866.78,1487.19 1866.78,1418.22 1940,1345 v2(1940,1000) 1940.44,1000 1940.44,997.72 v2@1937.28,997.72
  Top Layer w15: 783.11,1403.11 783.86,1403.86 788.86,1403.86 788.86,1156.14 783.86,1151.14
  Top Layer w20: v2(210,1925) 210,1870 150,1810 150,1095 220,1025 220,610 300,530 415,530 J2.38@465,580 600,580 700,480 J3.39@1565,480 1615,530 1715,530 1744,501 ; v2(310,2020) v2(310,2040) 310,2200 342,2232 384.88,2232 432.88,2280 J2.4@465,2280 ; 1027,575 v2(1027,585) MicroSD1.4@1027,679 C23.2@1027,758 ; C18.2@1280,1590 1280,1600 1295,1615 1325,1615 v2(1390,1680) ; v2(1320,1750) 1303,1767 1303,1812 1287,1828 R14.2@1250,1828 1250,1835 1190,1895 1190,2060 1415,2285 1415,2410 1370,2455 1350,2455 ; J3.2@1665,2380 1720,2380 1761,2339 C31.2@1761,2120 ; C36.2@1755,385.12 1744,396.12 1744,501 ; C31.2@1760,2119 1760,2085 ; U4.7@1810,2032.6 1810,2045 1770,2085 1760,2085 ; R17.2@1830,501 R18.2@1780,501 1744,501 ; U6.3@1859.72,1494.24 1859.72,1535.28 1840.12,1554.88 C34.2@1840.12,1600 1840.12,1645.12 1860,1665 U4.3@1860,1720 1860,1815 1760,1915 U4.8@1760,2032.6 1760,2085
  Top Layer w25: C16.2@695.5,1410.5 v2(711,1395) v2@720,1395
  Top Layer w30: J2.4@465,2280 535,2350 535,2460 620,2545 760,2545 ; C4.1@855,2585 800,2585 760,2545 ; J1.18@1279.92,2388.74 1208.66,2460 1155,2460 1040,2460 955,2545 760,2545
  Bottom Layer w8: v2(1870,997.72) v2@1937.72,997.72
  Bottom Layer w15: v2(690,1495) 727.5,1457.5 727.5,1411.5 v2(711,1395)
  Bottom Layer w20: J1.18@1279.92,2388.74 1279.92,2399.92 v2(1340,2460) ; v2(1320,1750) v2(1390,1680) ; v2(1340,2480) 1345,2480 1345,2465 v2(1340,2460) ; J3.2@1665,2380 1585,2460 v2(1340,2460)
  other v2: 1025,470 1025,490 1025,565 825,2085 845,2085 590,2105 620,2105 825,2110 845,2110
CSI_MCLK: CN2.12 J3.20 MicroSD1.1 U1.53 | length 1978.2
  Top Layer w6: U1.53@1146.85,1245.63 1240.63,1245.63 1250,1255 1253.28,1255 1345.28,1347 1407,1347 ; MicroSD1.1@1159,679 1159,749 1224.69,814.69 1224.69,930.31 v2(1219.69,930.31) ; v2(1480,1150) 1480,1274 1407,1347 ; J3.20@1665,1480 1615,1430 1490,1430 1407,1347 ; CN2.12@1771,958.98 v2(1823.98,958.98)
  Bottom Layer w6: v2(1219.69,930.31) 1219.69,1244.69 1230,1255 v2(1245,1255) ; v2(1480,1150) 1480,1095 1545,1030 1685,1030 1730,985 1797.96,985 v2(1823.98,958.98)
CSI_PCLK: CN2.8 J3.25 U1.47 | length 956
  Top Layer w6: U1.47@1146.85,1151.14 1168.86,1151.14 1238,1082 1334.62,1082 1349.91,1066.7 1468.47,1066.7 1529.62,1127.85 1529.62,1148 1561.62,1180 J3.25@1565,1180 1580,1180 1630,1130 1675,1130 1745.25,1059.75 1745.25,925.25 1735,915 1735,890 1744.76,880.24 CN2.8@1771,880.24
CSI_PWDN: CN2.17 J3.15 MicroSD1.8 R16.2 U1.58 | length 2502.1
  Top Layer w6: MicroSD1.8@851,679 851,726 883,758 943,758 1080,895 v2(1080,910) ; U1.58@1146.85,1324.37 1185.99,1324.37 1249.62,1388 1249.72,1388 1261,1399.28 1261,1399.38 1266.62,1405 v2@1270,1405 ; v2@1275,1410 v2(1280,1405) ; v2@1281,1406 v2(1280,1405) ; v2(1745,1255) R16.2@1745,1296 1768.88,1319.88 1768.88,1351.12 1730,1390 1730,1506.62 1717,1519.62 1717,1710 1706,1721 1614,1721 1573,1680 J3.15@1565,1680 1565,1668.38 1474.26,1577.65 1474.26,1509.41 1376.85,1412 1308.46,1412 1301.46,1405 v2(1280,1405) ; CN2.17@1771,1057.41 1825,1057.41 v2(1825,1060)
  Bottom Layer w6: v2(1080,910) 1080,946.46 1154.69,1021.15 1154.69,1292.98 1266.72,1405 v2(1280,1405) ; v2(1745,1255) 1825,1175 v2(1825,1060)
CSI_RST: CN2.19 J3.19 MicroSD1.2 U1.54 | length 1807.7
  Top Layer w6: MicroSD1.2@1115,679 1115,740 1190,815 v2(1190,930) ; U1.54@1146.85,1261.38 1223.09,1261.38 1246.72,1285 v2(1255,1285) 1330,1360 1400,1360 1520,1480 J3.19@1565,1480 1585,1480 1635,1530 1684,1530 1717,1497 1717,1126.38 1746.61,1096.78 CN2.19@1771,1096.78
  Bottom Layer w6: v2(1190,930) 1190,960 1206.69,976.69 1206.69,1256.69 1235,1285 v2(1255,1285)
CSI_SCL: CN2.20 J3.36 R18.1 U1.38 | length 1962.9
  Top Layer w6: U1.38@1020.87,1088.15 1020.87,1055.75 1111.62,965 1286.15,965 1521.15,730 1615,730 J3.36@1665,680 1687,680 1715,652 1752.77,652 1811.77,593 1914.62,593 1932,610.38 1932,738 1910,760 1910,1080 1873.54,1116.46 CN2.20@1771,1116.46 ; v1(1730,615) 1780,565 R18.1@1780,540
  Bottom Layer w6: J3.36@1665,680 v1(1730,615)
CSI_SDA: CN2.22 J3.35 R17.1 U1.37 | length 1892.9
  Top Layer w6: U1.37@1005.12,1088.15 1005.12,1053.11 1106.23,952 1280.77,952 1552.77,680 J3.35@1565,680 1606,639 1747.38,639 1806.38,580 1920,580 1945,605 1945,740.56 1921,764.56 1921,1089 1854.17,1155.83 CN2.22@1771,1155.83 ; R17.1@1830,540 1830,580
